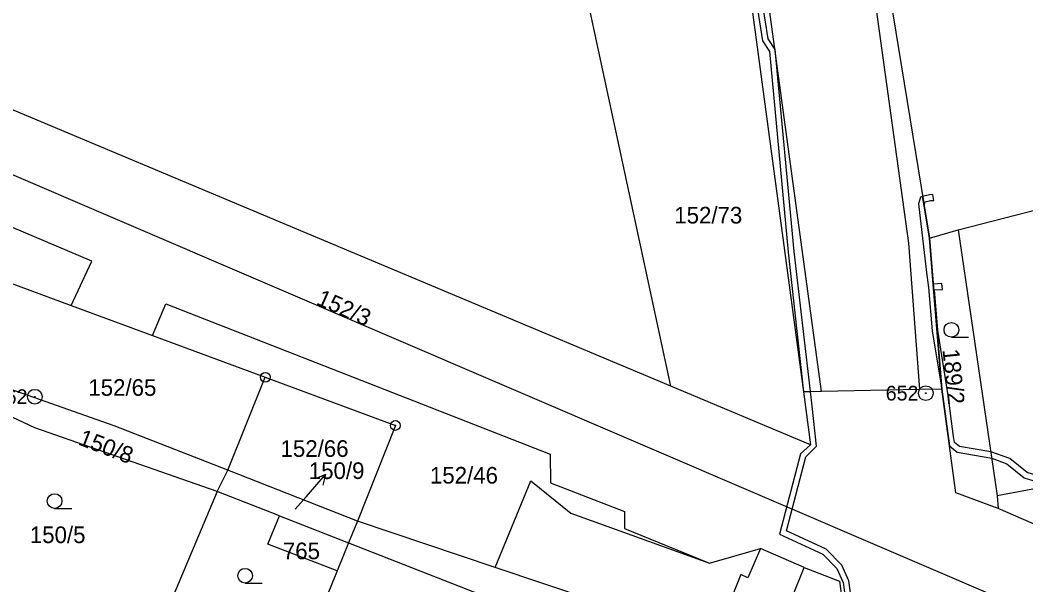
# Model space of a CAD drawing. Extents: x -783948 to -781889, y -1005870 to -1004430.
# Drawn here: x -783020.1 to -782917.3, y -1005041.6 to -1004983.9 of the extents above; entities that cross this region are included whole.
import ezdxf

# ---------------------------------------------------------------- set-up
doc = ezdxf.new("R2010")
doc.units = 0
for name, color, linetype in [('Vrstva 1', 7, 'Continuous'), ('Vrstva 13', 7, 'Continuous'), ('Vrstva 2', 7, 'Continuous'), ('Vrstva 3', 7, 'Continuous'), ('Vrstva 4', 7, 'Continuous'), ('Vrstva 6', 7, 'Continuous'), ('Vrstva 7', 7, 'Continuous'), ('Vrstva 8', 7, 'Continuous')]:
    doc.layers.add(name, color=color, linetype=linetype)

msp = doc.modelspace()

# ---------------------------------------------------------------- linework, layer by layer
at = {"layer": 'Vrstva 1'}
for p, q in [((-782953.56, -1005021.28), (-783115.01, -1004953.5)), ((-782932.67, -1004972.37), (-782927.15, -1005006.15)), ((-782953.56, -1005021.28), (-782962.02, -1004982.04)), ((-782945.37, -1004982.08), (-782940.02, -1005021.84)), ((-782924.2, -1005005.29), (-782908.62, -1005001.3)), ((-782927.15, -1005006.15), (-782924.2, -1005005.29)), ((-782924.2, -1005005.29), (-782920.21, -1005032.48)), ((-782927.15, -1005006.15), (-782925.88, -1005021.59)), ((-783023.02, -1005010.02), (-783014.85, -1005013.04)), ((-783014.85, -1005013.04), (-783006.56, -1005016.1)), ((-783006.56, -1005016.1), (-782995.02, -1005020.37)), ((-782998.86, -1005029.87), (-782995.02, -1005020.37)), ((-782995.02, -1005020.37), (-782981.72, -1005025.29)), ((-782981.72, -1005025.29), (-782985.59, -1005035.06)), ((-782900.7, -1005028.79), (-782920.21, -1005032.48)), ((-782999.94, -1005032.04), (-782998.86, -1005029.87)), ((-782985.59, -1005035.06), (-782998.86, -1005029.87)), ((-782971.51, -1005039.79), (-782967.89, -1005030.95)), ((-782999.94, -1005032.04), (-783006.14, -1005046.74)), ((-782993.57, -1005034.53), (-782999.94, -1005032.04)), ((-782920.21, -1005032.48), (-782920.12, -1005033.77)), ((-782899.77, -1005042.67), (-782920.12, -1005033.77)), ((-782993.57, -1005034.53), (-782986.5, -1005037.29)), ((-782985.59, -1005035.06), (-782986.5, -1005037.29)), ((-782971.51, -1005039.79), (-782985.59, -1005035.06)), ((-782986.5, -1005037.29), (-782987.66, -1005040.14)), ((-782986.5, -1005037.29), (-782972.67, -1005042.7)), ((-782949.63, -1005039.35), (-782944.42, -1005037.87)), ((-782939.93, -1005039.81), (-782944.42, -1005037.87)), ((-782987.66, -1005040.14), (-782992.39, -1005051.79)), ((-782939.93, -1005039.81), (-782936.33, -1005041.21)), ((-782936.33, -1005041.21), (-782934.89, -1005052.11))]:
    msp.add_line(p, q, dxfattribs=at)
for points in [[(-783014.85, -1005013.04), (-783012.76, -1005008.51), (-783056.45, -1004989.98)], [(-783006.56, -1005016.1), (-783005.19, -1005012.86), (-782965.9, -1005028.22), (-782965.86, -1005031.14), (-782958.32, -1005034.09), (-782958.3, -1005035.81), (-782949.63, -1005039.35)], [(-782998.86, -1005029.87), (-783010.46, -1005025.33), (-783026.93, -1005019.54)], [(-782999.94, -1005032.04), (-783018.56, -1005025.52), (-783027.65, -1005021.28)], [(-782940.02, -1005021.84), (-782939.29, -1005027.27), (-782953.56, -1005021.28)], [(-782925.88, -1005021.59), (-782928.16, -1005021.63), (-782938.18, -1005021.81), (-782940.02, -1005021.84)], [(-782920.12, -1005033.77), (-782924.46, -1005032.18), (-782925.88, -1005021.59)], [(-782967.89, -1005030.95), (-782963.79, -1005034.24), (-782949.63, -1005039.35)], [(-782987.66, -1005040.14), (-782994.76, -1005037.43), (-782993.57, -1005034.53)], [(-782944.42, -1005037.87), (-782945.71, -1005040.85), (-782946.4, -1005040.51)], [(-782936.14, -1005061.11), (-782948.86, -1005057.63), (-782956.51, -1005044.83), (-782971.51, -1005039.79)], [(-782943.48, -1005050.96), (-782942.96, -1005049.67), (-782940.7, -1005050.58), (-782939.25, -1005046.99), (-782941.54, -1005046.07), (-782940.33, -1005043.07), (-782941.12, -1005042.76), (-782939.93, -1005039.81)], [(-782946.4, -1005040.51), (-782949.63, -1005048.48), (-782943.48, -1005050.96)]]:
    msp.add_lwpolyline(points, dxfattribs=at)
at = {"layer": 'Vrstva 13'}
for points in [[(-782944.37, -1004981.04), (-782945.6, -1004980.38), (-782946.58, -1004979.86), (-782948.8, -1004979.67), (-782948.77, -1004980.28), (-782946.76, -1004980.44), (-782945.5, -1004981.11), (-782944.91, -1004981.42), (-782944.19, -1004985.99), (-782943.48, -1004987.08), (-782941.58, -1005007.59), (-782940.02, -1005021.84), (-782939.31, -1005021.83), (-782940.98, -1005007.53), (-782942.9, -1004986.88), (-782943.61, -1004985.77)], [(-782925.88, -1005021.59), (-782926.76, -1005010.84), (-782927.15, -1005006.15), (-782927.69, -1005002.86), (-782927.84, -1005001.9), (-782928.07, -1005001.96), (-782928.25, -1005002.64), (-782927.43, -1005009.66), (-782927.24, -1005011.18), (-782926.87, -1005015.61)], [(-782927.84, -1005001.9), (-782927.69, -1005002.86), (-782927.58, -1005002.45), (-782927.04, -1005002.3), (-782926.69, -1005002.29), (-782926.78, -1005001.69), (-782927.13, -1005001.71)], [(-782914.81, -1005031.46), (-782913.6, -1005031.23), (-782913.86, -1005031.12), (-782917.17, -1005030.11), (-782918.92, -1005028.68), (-782920.87, -1005027.98), (-782924.06, -1005027.45), (-782924.57, -1005027.04), (-782924.67, -1005026.43), (-782925.23, -1005022.23), (-782926.27, -1005015.54), (-782926.61, -1005011.43), (-782925.81, -1005011.38), (-782925.86, -1005010.78), (-782926.76, -1005010.84), (-782925.88, -1005021.59), (-782925.1, -1005027.38), (-782924.32, -1005028.01), (-782920.78, -1005028.62), (-782919.22, -1005029.2), (-782917.46, -1005030.65)], [(-782940.02, -1005021.84), (-782939.29, -1005027.27), (-782940.33, -1005028.2), (-782942.46, -1005036.39), (-782938.04, -1005038.43), (-782936.61, -1005039.91), (-782935.96, -1005041.32), (-782935.24, -1005046.58), (-782934.7, -1005052.11), (-782934.09, -1005052.1), (-782934.64, -1005046.5), (-782935.38, -1005041.16), (-782936.11, -1005039.57), (-782937.68, -1005037.93), (-782941.76, -1005036.05), (-782939.79, -1005028.48), (-782938.7, -1005027.41), (-782939.13, -1005023.32), (-782939.31, -1005021.83)]]:
    msp.add_lwpolyline(points, close=True, dxfattribs=at)
at = {"layer": 'Vrstva 3'}
for p, q in [((-782924.9, -1005016.27), (-782923.15, -1005016.27)), ((-783016.55, -1005033.76), (-783014.8, -1005033.76)), ((-782997.08, -1005041.39), (-782995.33, -1005041.39))]:
    msp.add_line(p, q, dxfattribs=at)
for centre in [(-782924.9, -1005015.52), (-783016.55, -1005033.01), (-782997.08, -1005040.64)]:
    msp.add_circle(centre, 0.75, dxfattribs=at)
at = {"layer": 'Vrstva 4'}
for p, q in [((-782938.18, -1005021.81), (-782948.3, -1004947.37)), ((-782936.21, -1004956.75), (-782929.27, -1005006.66)), ((-782929.27, -1005006.66), (-782928.16, -1005021.63))]:
    msp.add_line(p, q, dxfattribs=at)
at = {"layer": 'Vrstva 6'}
msp.add_line((-783060.19, -1004982.81), (-782841.72, -1005076.44), dxfattribs=at)
at = {"layer": 'Vrstva 7'}
for p, q in [((-782990.84, -1005032.57), (-782988.87, -1005030.31)), ((-782988.87, -1005030.31), (-782989.91, -1005030.73)), ((-782988.87, -1005030.31), (-782989.15, -1005031.39)), ((-782991.95, -1005033.85), (-782990.84, -1005032.57))]:
    msp.add_line(p, q, dxfattribs=at)
at = {"layer": 'Vrstva 8'}
for centre, radius in [((-782995.02, -1005020.37), 0.5), ((-782995.02, -1005020.37), 0.0303), ((-783018.57, -1005022.35), 0.75), ((-782927.51, -1005021.99), 0.75), ((-782927.51, -1005021.99), 0.03), ((-783018.57, -1005022.35), 0.03), ((-782981.72, -1005025.29), 0.5), ((-782981.72, -1005025.29), 0.0303)]:
    msp.add_circle(centre, radius, dxfattribs=at)

# ---------------------------------------------------------------- texts
at = {"layer": 'Vrstva 2'}
for s, p in [('152/73', (-782953.22, -1005004.65)), ('152/65', (-783013.1, -1005022.26)), ('152/66', (-782993.46, -1005028.5)), ('150/9', (-782990.57, -1005030.76)), ('152/46', (-782978.19, -1005031.23)), ('150/5', (-783019.08, -1005037.31)), ('765', (-782993.22, -1005038.96))]:
    msp.add_text(s, height=1.7, dxfattribs=at).set_placement(p)
for s, rotation, p in [('152/3', 336, (-782989.9, -1005012.88)), ('189/2', 276, (-782925.81, -1005017.55)), ('150/8', 339, (-783014.23, -1005027.21))]:
    msp.add_text(s, height=1.7, rotation=rotation, dxfattribs=at).set_placement(p)
at = {"layer": 'Vrstva 8'}
for s, p in [('262', (-783022.67, -1005023.1)), ('652', (-782931.61, -1005022.74))]:
    msp.add_text(s, height=1.5, dxfattribs=at).set_placement(p)

doc.saveas('drawing.dxf')
